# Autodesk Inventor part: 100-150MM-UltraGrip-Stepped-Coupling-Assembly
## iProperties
Created: 2012-05
Part Number: 100-150MM-UltraGrip-Stepped-Coupling-Assembly
Document SubType Name: Modeling
Designer: D Cole
Density: 1 g/cm^3
Author: D Cole
